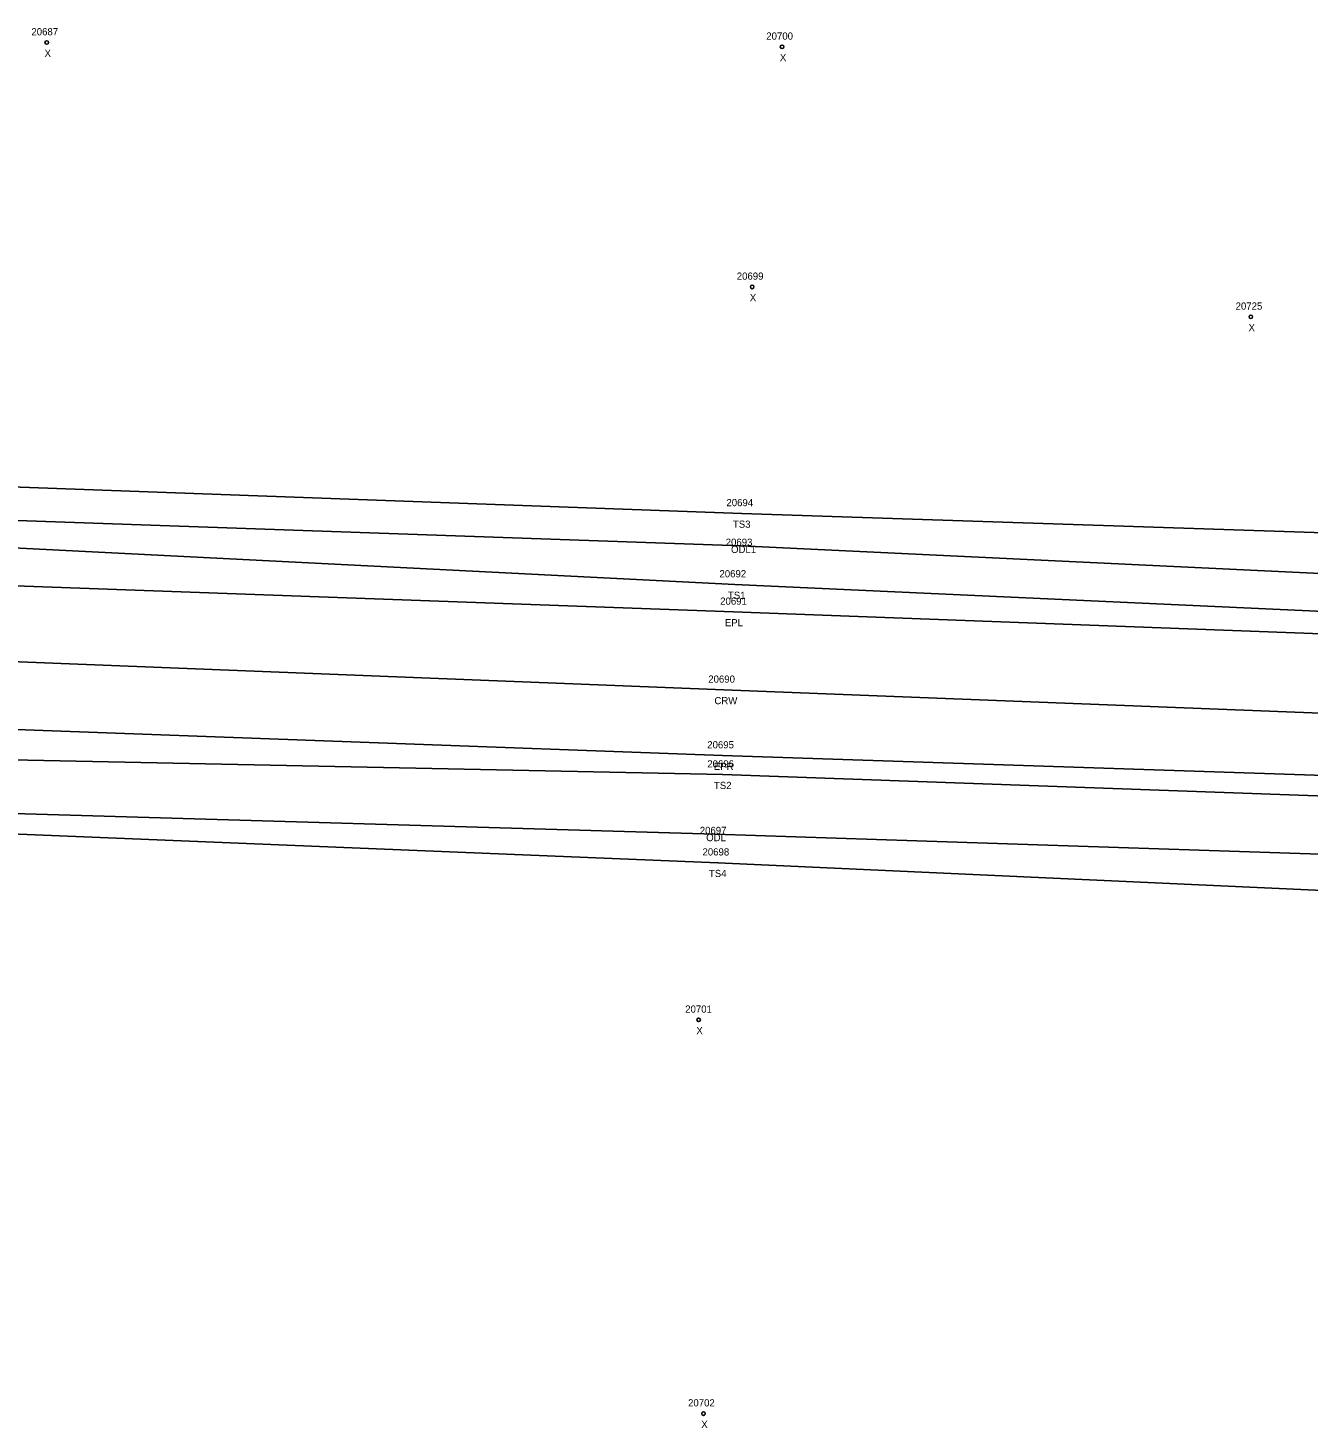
# Model space of a CAD drawing. Extents: x 1966740 to 1969291, y 1117378 to 1118461.
# Drawn here: x 1968685 to 1968863.2, y 1117801.8 to 1117996.6 of the extents above; entities that cross this region are included whole.
import ezdxf

# ---------------------------------------------------------------- set-up
doc = ezdxf.new("R2010")
doc.units = 0
for name, color, linetype in [('RD_DTM_BkLn1', 7, 'Continuous'), ('RD_DTM_BkLn2', 7, 'Continuous'), ('RD_EX_H2O', 7, 'Continuous'), ('RD_EX_H2O_txCode', 7, 'Continuous'), ('RD_EX_Road', 7, 'Continuous'), ('RD_EX_Road_txCode', 7, 'Continuous'), ('RD_SMD_Locator', 7, 'Continuous'), ('RD_SMD_Misc', 7, 'Continuous')]:
    doc.layers.add(name, color=color, linetype=linetype)

msp = doc.modelspace()

# ---------------------------------------------------------------- linework, layer by layer
at = {"layer": 'RD_DTM_BkLn1'}
msp.add_lwpolyline([(1968529.36, 1117916.3), (1968681.48, 1117908.5), (1968781.89, 1117904.51), (1968887.49, 1117900.39), (1968989.06, 1117896.4), (1969090.87, 1117891.24), (1969190.23, 1117887.94), (1969284.4, 1117884.73)], dxfattribs=at)
at = {"layer": 'RD_DTM_BkLn2'}
for points in [[(1968532.27, 1117940.77), (1968682.68, 1117932.75), (1968784.38, 1117929.07), (1968872.44, 1117926.13)], [(1968531.49, 1117931.42), (1968682.06, 1117924.3), (1968783.42, 1117919.17), (1968888.7, 1117914.33), (1968991.06, 1117912.02), (1969093.07, 1117907.16), (1969191.83, 1117902.92), (1969283.72, 1117899.63)], [(1968528.99, 1117899.6), (1968680.45, 1117894.84), (1968781.74, 1117892.71), (1968887.7, 1117888.94), (1968987.81, 1117885.08), (1969089.75, 1117880.01), (1969189.02, 1117876.39), (1969282.76, 1117873.05)], [(1968528.68, 1117880.51), (1968680.3, 1117884.55), (1968781.05, 1117880.46), (1968887.57, 1117875.57), (1968986, 1117872.85), (1969087.95, 1117867.56), (1969189.32, 1117864.4), (1969289.73, 1117862.33)]]:
    msp.add_lwpolyline(points, dxfattribs=at)
at = {"layer": 'RD_EX_H2O'}
for points in [[(1968531.76, 1117937.18), (1968682.22, 1117928.11), (1968784.28, 1117924.56), (1968890.2, 1117919.49), (1968991.22, 1117915.37), (1969093.76, 1117910.9), (1969192.08, 1117906.24), (1969283.24, 1117903.06)], [(1968528.55, 1117888.35), (1968679.78, 1117887.39), (1968780.67, 1117884.45), (1968887.36, 1117880.9), (1968987.02, 1117877.31), (1969088.58, 1117870.53), (1969189.53, 1117868.6), (1969284.94, 1117865.64)]]:
    msp.add_lwpolyline(points, dxfattribs=at)
at = {"layer": 'RD_EX_Road'}
for points in [[(1968530.54, 1117925.7), (1968681.97, 1117919.01), (1968783.23, 1117915.36), (1968888.64, 1117911.44), (1968991.22, 1117907.09), (1969091.98, 1117903.06), (1969191.09, 1117898.66), (1969283.27, 1117895.43)], [(1968527.82, 1117906.41), (1968680.79, 1117899.07), (1968781.71, 1117895.37), (1968887.86, 1117891.84), (1968988.65, 1117888.23), (1969090.1, 1117882.83), (1969189.3, 1117879.04), (1969282.94, 1117875.42)]]:
    msp.add_lwpolyline(points, dxfattribs=at)
at = {"layer": 'RD_SMD_Locator'}
for centre, radius in [((1968687.63, 1117994.6), 0.25), ((1968789.99, 1117994), 0.25), ((1968785.82, 1117960.59), 0.25), ((1968855.24, 1117956.42), 0.25), ((1968784.38, 1117929.07), 0.001), ((1968784.28, 1117924.56), 0.001), ((1968783.42, 1117919.17), 0.001), ((1968783.23, 1117915.36), 0.001), ((1968781.89, 1117904.51), 0.001), ((1968781.71, 1117895.37), 0.001), ((1968781.74, 1117892.71), 0.001), ((1968780.67, 1117884.45), 0.001), ((1968781.05, 1117880.46), 0.001), ((1968778.37, 1117858.59), 0.25), ((1968779.05, 1117803.79), 0.25)]:
    msp.add_circle(centre, radius, dxfattribs=at)

# ---------------------------------------------------------------- texts
at = {"layer": 'RD_EX_H2O_txCode'}
for s, p in [('20693', (1968782.14, 1117924.56)), ('ODL1', (1968782.88, 1117923.56)), ('20697', (1968778.53, 1117884.45)), ('ODL', (1968779.42, 1117883.45))]:
    msp.add_text(s, height=1, dxfattribs=at).set_placement(p)
at = {"layer": 'RD_EX_Road_txCode'}
for s, p in [('20691', (1968781.37, 1117916.36)), ('EPL', (1968782.02, 1117913.36)), ('20695', (1968779.57, 1117896.37)), ('EPR', (1968780.48, 1117893.37))]:
    msp.add_text(s, height=1, dxfattribs=at).set_placement(p)
at = {"layer": 'RD_SMD_Misc'}
for s, p in [('20687', (1968685.49, 1117995.6)), ('20700', (1968787.79, 1117995)), ('X', (1968687.32, 1117992.6)), ('X', (1968789.68, 1117992)), ('20699', (1968783.68, 1117961.59)), ('X', (1968785.5, 1117958.59)), ('20725', (1968853.12, 1117957.42)), ('X', (1968854.92, 1117954.42)), ('20694', (1968782.24, 1117930.07)), ('TS3', (1968783.14, 1117927.07)), ('20692', (1968781.27, 1117920.17)), ('TS1', (1968782.45, 1117917.17)), ('20690', (1968779.71, 1117905.51)), ('CRW', (1968780.57, 1117902.51)), ('20696', (1968779.58, 1117893.71)), ('TS2', (1968780.5, 1117890.71)), ('20698', (1968778.91, 1117881.46)), ('TS4', (1968779.8, 1117878.46)), ('20701', (1968776.5, 1117859.59)), ('X', (1968778.06, 1117856.59)), ('20702', (1968776.9, 1117804.79)), ('X', (1968778.74, 1117801.79))]:
    msp.add_text(s, height=1, dxfattribs=at).set_placement(p)

doc.saveas('drawing.dxf')
